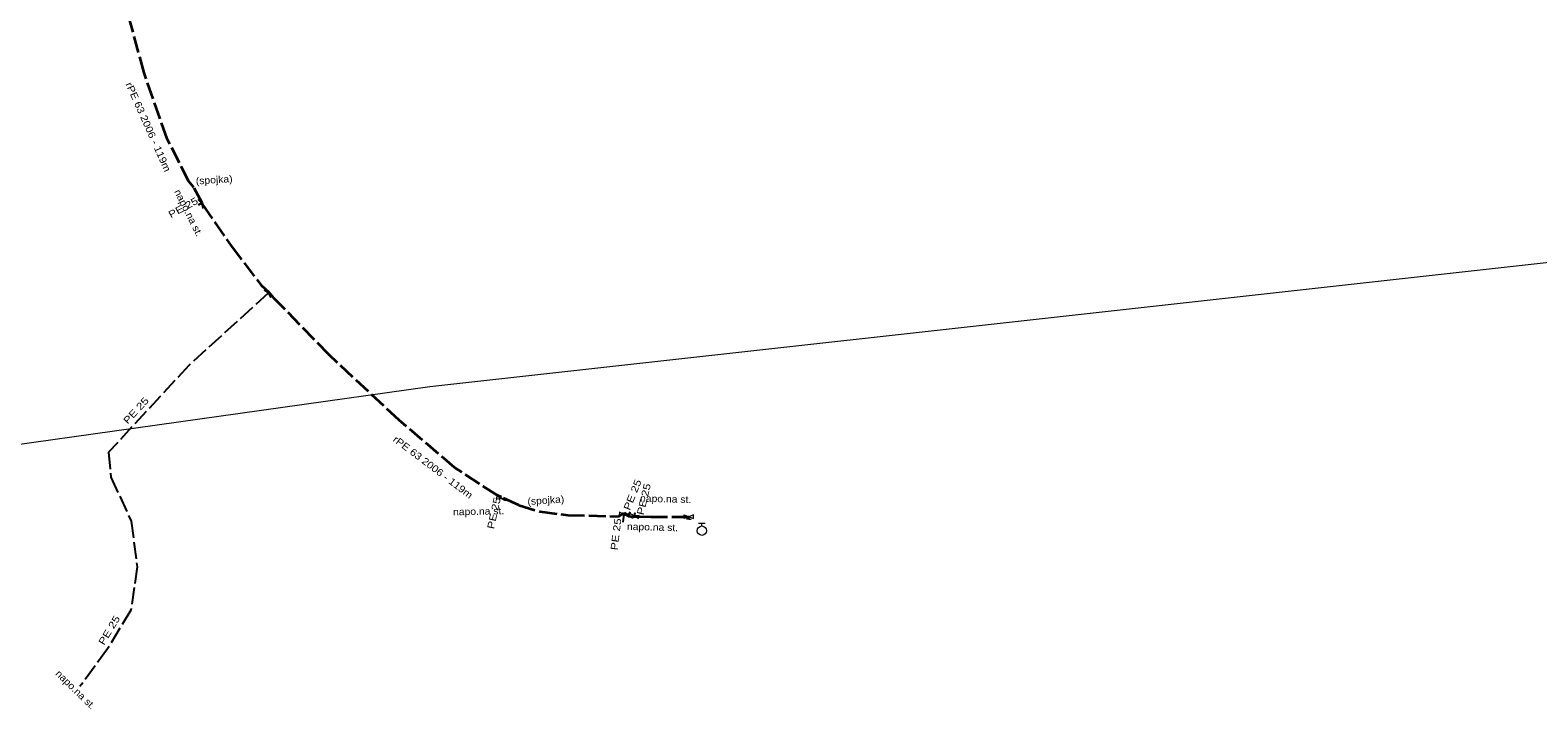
# Model space of a CAD drawing. Extents: x -582626 to -580899, y -1097611 to -1096610.
# Drawn here: x -581940.6 to -581779.8, y -1097238.1 to -1097164.8 of the extents above; entities that cross this region are included whole.
import ezdxf
from ezdxf.enums import TextEntityAlignment as Align

# ---------------------------------------------------------------- set-up
doc = ezdxf.new("R2010")
doc.units = 0
doc.header["$LTSCALE"] = 0.3
doc.linetypes.add('LONG_DASHED', pattern=[7.5, 6, -1.5])
for name, color, linetype, lineweight in [('1', 7, 'Continuous', 13), ('10', 7, 'Continuous', 13), ('35', 7, 'LONG_DASHED', 35), ('50', 7, 'LONG_DASHED', 25)]:
    doc.layers.add(name, color=color, linetype=linetype, lineweight=lineweight)
doc.layers.add('16', color=7, linetype='Continuous')
doc.layers.add('19', color=7, linetype='Continuous')

msp = doc.modelspace()

# ---------------------------------------------------------------- linework, layer by layer
at = {"layer": '1'}
msp.add_lwpolyline([(-582625.57, -1097394.66), (-582612.34, -1097467.421), (-582321.299, -1097262.369), (-581897.965, -1097202.837), (-581719.372, -1097182.994), (-581593.695, -1097110.233), (-581382.028, -1096971.327), (-581362.184, -1096819.192), (-581322.497, -1096739.817), (-581210.049, -1096733.202), (-581097.601, -1096686.9), (-580905.778, -1096719.973), (-580899.163, -1096627.369), (-581084.372, -1096614.14), (-581216.663, -1096680.285), (-581368.799, -1096686.9), (-581434.945, -1096812.577), (-581468.018, -1096971.327), (-581659.84, -1097004.4), (-581831.82, -1097110.233), (-582314.684, -1097169.765), (-582519.736, -1097295.442), (-582625.57, -1097394.66)], close=True, dxfattribs=at)
at = {"layer": '10'}
for p, q in [((-581870.34, -1097216.989), (-581870.09, -1097216.988)), ((-581869.295, -1097217.428), (-581868.595, -1097217.428)), ((-581868.945, -1097217.728), (-581868.945, -1097217.428))]:
    msp.add_line(p, q, dxfattribs=at)
for points in [[(-581922.319, -1097183.302), (-581922.69, -1097182.935), (-581922.427, -1097182.791), (-581922.319, -1097183.302), (-581922.211, -1097183.813), (-581921.948, -1097183.669)], [(-581915.199, -1097192.887), (-581915.647, -1097192.618), (-581915.425, -1097192.416), (-581915.199, -1097192.887), (-581914.973, -1097193.358), (-581914.751, -1097193.156)], [(-581890.353, -1097214.784), (-581889.832, -1097214.746), (-581889.897, -1097215.039), (-581890.353, -1097214.784), (-581890.809, -1097214.529), (-581890.874, -1097214.822)], [(-581877.274, -1097216.466), (-581876.759, -1097216.381), (-581876.797, -1097216.678), (-581877.274, -1097216.466), (-581877.751, -1097216.254), (-581877.789, -1097216.551)], [(-581876.746, -1097216.62), (-581876.226, -1097216.667), (-581876.338, -1097216.945), (-581876.746, -1097216.62), (-581877.154, -1097216.295), (-581877.266, -1097216.573)], [(-581876.153, -1097216.653), (-581876.674, -1097216.683), (-581876.605, -1097216.391), (-581876.153, -1097216.653), (-581875.701, -1097216.915), (-581875.632, -1097216.623)]]:
    msp.add_lwpolyline(points, close=True, dxfattribs=at)
msp.add_lwpolyline([(-581870.341, -1097216.739), (-581870.84, -1097216.928), (-581870.842, -1097216.554), (-581870.341, -1097216.739), (-581869.84, -1097216.924), (-581869.842, -1097216.55), (-581870.341, -1097216.739), (-581870.34, -1097216.989), (-581870.59, -1097216.99)], dxfattribs=at)
msp.add_circle((-581868.945, -1097218.228), 0.5, dxfattribs=at)
at = {"layer": '35'}
for p, q in [((-581877.282, -1097216.362), (-581876.807, -1097216.691)), ((-581876.807, -1097216.691), (-581876.196, -1097216.723))]:
    msp.add_line(p, q, dxfattribs=at)
for points in [[(-581923.124, -1097181.605), (-581923.656, -1097180.992), (-581925.99, -1097176.415), (-581928.438, -1097169.399), (-581930.127, -1097163.204), (-581931.156, -1097157.791), (-581931.542, -1097152.159), (-581931.077, -1097149.404)], [(-581922.225, -1097183.446), (-581922.241, -1097183.262), (-581923.124, -1097181.605)], [(-581922.225, -1097183.446), (-581919.143, -1097187.857), (-581915.961, -1097192.036), (-581915.106, -1097192.827)], [(-581890.792, -1097214.448), (-581895.318, -1097211.493), (-581901.23, -1097206.455), (-581908.7, -1097199.484), (-581914.562, -1097193.445), (-581915.106, -1097192.827)], [(-581888.479, -1097215.522), (-581890.324, -1097214.653), (-581890.792, -1097214.448)], [(-581888.479, -1097215.522), (-581886.216, -1097216.189), (-581883.258, -1097216.564), (-581877.853, -1097216.707), (-581877.282, -1097216.362)], [(-581876.196, -1097216.723), (-581874.408, -1097216.755), (-581870.341, -1097216.739)]]:
    msp.add_lwpolyline(points, dxfattribs=at)
at = {"layer": '50'}
for p, q in [((-581922.319, -1097183.302), (-581922.663, -1097183.49)), ((-581922.241, -1097183.262), (-581922.319, -1097183.302)), ((-581915.106, -1097192.827), (-581915.199, -1097192.887)), ((-581890.353, -1097214.784), (-581890.324, -1097214.653)), ((-581877.274, -1097216.466), (-581877.383, -1097217.319)), ((-581877.282, -1097216.362), (-581877.274, -1097216.466)), ((-581876.807, -1097216.691), (-581876.746, -1097216.62)), ((-581876.746, -1097216.62), (-581876.587, -1097216.223))]:
    msp.add_line(p, q, dxfattribs=at)
for points in [[(-581915.199, -1097192.887), (-581923.619, -1097200.557), (-581932.232, -1097209.869), (-581931.993, -1097212.523), (-581929.812, -1097217.206), (-581929.186, -1097222.075), (-581929.855, -1097226.71), (-581932.328, -1097230.822), (-581935.29, -1097234.867)], [(-581876.196, -1097216.723), (-581876.153, -1097216.653), (-581876.063, -1097216.276)]]:
    msp.add_lwpolyline(points, dxfattribs=at)

# ---------------------------------------------------------------- texts
at = {"layer": '16'}
for s, rotation, width, p in [('rPE 63 2006 - 119m', 293.947, 1.15, (-581928.3391, -1097175.3078)), ('(spojka)', 3.874, 1.1, (-581920.9403, -1097181.1676)), ('rPE 63 2006 - 119m', 322.888, 1.15, (-581897.8583, -1097211.7439)), ('(spojka)', 3.874, 1.1, (-581885.5698, -1097215.3545))]:
    msp.add_text(s, height=0.75, rotation=rotation, dxfattribs=dict(at, width=width)).set_placement(p, align=Align.CENTER)
at = {"layer": '19'}
for s, rotation, width, p in [('napo.na st.', 296.541, 1.1, (-581924.032, -1097184.4829)), ('PE 25', 28.657, 1.25, (-581924.0888, -1097184.0924)), ('PE 25', 47.233, 1.25, (-581929.0272, -1097205.6666)), ('PE 25', 68.174, 1.25, (-581876.002, -1097214.5409)), ('PE 25', 76.573, 1.25, (-581874.7777, -1097214.9556)), ('napo.na st.', 1.355, 1.1, (-581892.7524, -1097216.5356)), ('PE 25', 77.518, 1.25, (-581890.7643, -1097216.4386)), ('napo.na st.', 358.484, 1.1, (-581872.8204, -1097215.2082)), ('PE 25', 82.718, 1.25, (-581877.7406, -1097218.6525)), ('napo.na st.', 358.484, 1.1, (-581874.2224, -1097218.2162)), ('PE 25', 58.977, 1.25, (-581931.8395, -1097229.0393)), ('napo.na st.', 315.628, 1.1, (-581936.0012, -1097235.462))]:
    msp.add_text(s, height=0.75, rotation=rotation, dxfattribs=dict(at, width=width)).set_placement(p, align=Align.CENTER)

doc.saveas('drawing.dxf')
